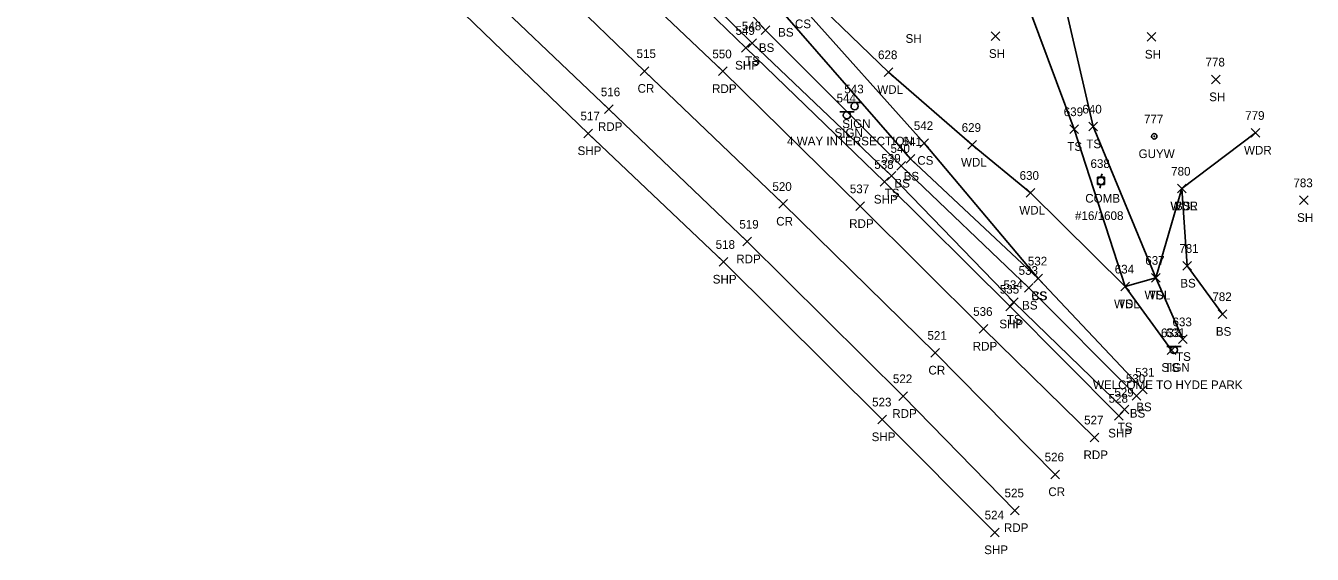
# Model space of a CAD drawing. Extents: x 1611034 to 1613847, y 761049 to 763902.
# Drawn here: x 1611761.1 to 1612057.6, y 762926.8 to 763048.6 of the extents above; entities that cross this region are included whole.
import ezdxf

# ---------------------------------------------------------------- set-up
doc = ezdxf.new("R2010")
doc.units = 0
for name, color, linetype in [('L_A', 7, 'Continuous'), ('L_I', 7, 'Continuous'), ('L_TIC', 7, 'Continuous'), ('LAWA', 7, 'Continuous'), ('LELB', 7, 'Continuous'), ('P_A', 7, 'Continuous'), ('P_I', 7, 'Continuous'), ('P_TIC', 7, 'Continuous'), ('PET', 7, 'Continuous'), ('PRC', 7, 'Continuous'), ('PSP', 7, 'Continuous'), ('S_A', 7, 'Continuous'), ('S_C', 7, 'Continuous'), ('S_I', 7, 'Continuous'), ('SSGN', 7, 'Continuous'), ('U_A', 7, 'Continuous'), ('U_C', 7, 'Continuous'), ('U_I', 7, 'Continuous'), ('UP', 7, 'Continuous'), ('UPGW', 7, 'Continuous')]:
    doc.layers.add(name, color=color, linetype=linetype)

msp = doc.modelspace()

# ---------------------------------------------------------------- linework, layer by layer
at = {"layer": 'L_TIC'}
for points in [[(1611930.63, 763046.56), (1611932.63, 763048.56)], [(1611932.63, 763046.56), (1611930.63, 763048.56)], [(1611927.51, 763043.56), (1611929.51, 763045.56)], [(1611929.51, 763043.56), (1611927.51, 763045.56)], [(1611983.61, 763045.19), (1611985.61, 763047.19)], [(1611985.61, 763045.19), (1611983.61, 763047.19)], [(1612019.56, 763045.03), (1612021.56, 763047.03)], [(1612021.56, 763045.03), (1612019.56, 763047.03)], [(1611958.95, 763036.9), (1611960.95, 763038.9)], [(1611960.95, 763036.9), (1611958.95, 763038.9)], [(1612034.39, 763035.21), (1612036.39, 763037.21)], [(1612036.39, 763035.21), (1612034.39, 763037.21)], [(1612001.76, 763023.77), (1612003.76, 763025.77)], [(1612003.76, 763023.77), (1612001.76, 763025.77)], [(1612006.15, 763024.37), (1612008.15, 763026.37)], [(1612008.15, 763024.37), (1612006.15, 763026.37)], [(1612043.55, 763022.91), (1612045.55, 763024.91)], [(1612045.55, 763022.91), (1612043.55, 763024.91)], [(1611967.15, 763020.56), (1611969.15, 763022.56)], [(1611969.15, 763020.56), (1611967.15, 763022.56)], [(1611978.24, 763020.14), (1611980.24, 763022.14)], [(1611980.24, 763020.14), (1611978.24, 763022.14)], [(1611964, 763016.91), (1611966, 763018.91)], [(1611966, 763016.91), (1611964, 763018.91)], [(1611959.67, 763013.03), (1611961.67, 763015.03)], [(1611961.67, 763013.03), (1611959.67, 763015.03)], [(1611961.87, 763015.31), (1611963.87, 763017.31)], [(1611963.87, 763015.31), (1611961.87, 763017.31)], [(1612026.56, 763010.05), (1612028.56, 763012.05)], [(1612028.56, 763010.05), (1612026.56, 763012.05)], [(1612026.56, 763010.05), (1612028.56, 763012.05)], [(1612028.56, 763010.05), (1612026.56, 763012.05)], [(1612026.56, 763010.05), (1612028.56, 763012.05)], [(1612028.56, 763010.05), (1612026.56, 763012.05)], [(1611991.68, 763009.08), (1611993.68, 763011.08)], [(1611993.68, 763009.08), (1611991.68, 763011.08)], [(1612054.66, 763007.38), (1612056.66, 763009.38)], [(1612056.66, 763007.38), (1612054.66, 763009.38)], [(1612027.77, 762992.25), (1612029.77, 762994.25)], [(1612029.77, 762992.25), (1612027.77, 762994.25)], [(1611993.45, 762989.34), (1611995.45, 762991.34)], [(1611995.45, 762989.34), (1611993.45, 762991.34)], [(1611993.45, 762989.34), (1611995.45, 762991.34)], [(1611995.45, 762989.34), (1611993.45, 762991.34)], [(1612020.56, 762989.5), (1612022.56, 762991.5)], [(1612022.56, 762989.5), (1612020.56, 762991.5)], [(1612020.56, 762989.5), (1612022.56, 762991.5)], [(1612022.56, 762989.5), (1612020.56, 762991.5)], [(1611991.31, 762987.18), (1611993.31, 762989.18)], [(1611993.31, 762987.18), (1611991.31, 762989.18)], [(1612013.52, 762987.49), (1612015.52, 762989.49)], [(1612015.52, 762987.49), (1612013.52, 762989.49)], [(1612013.52, 762987.49), (1612015.52, 762989.49)], [(1612015.52, 762987.49), (1612013.52, 762989.49)], [(1611987.81, 762983.91), (1611989.81, 762985.91)], [(1611989.81, 762983.91), (1611987.81, 762985.91)], [(1612035.97, 762981.13), (1612037.97, 762983.13)], [(1612037.97, 762981.13), (1612035.97, 762983.13)], [(1612026.83, 762975.33), (1612028.83, 762977.33)], [(1612028.83, 762975.33), (1612026.83, 762977.33)], [(1612024.16, 762972.81), (1612026.16, 762974.81)], [(1612026.16, 762972.81), (1612024.16, 762974.81)], [(1612017.61, 762963.73), (1612019.61, 762965.73)], [(1612019.61, 762963.73), (1612017.61, 762965.73)], [(1612016.14, 762962.27), (1612018.14, 762964.27)], [(1612018.14, 762962.27), (1612016.14, 762964.27)], [(1612013.39, 762959.1), (1612015.39, 762961.1)], [(1612015.39, 762959.1), (1612013.39, 762961.1)]]:
    msp.add_lwpolyline(points, dxfattribs=at)
at = {"layer": 'LAWA'}
for points in [[(1611776.19, 763209.71), (1611798.35, 763193.21), (1611821.91, 763171.59), (1611835.23, 763154.9), (1611840.73, 763150.36), (1611854.8, 763137.66), (1611869.74, 763122.61), (1611885.36, 763108.52), (1611898.9, 763094.55), (1611920.73, 763076.3), (1611936.34, 763060.75), (1611959.95, 763037.9), (1611979.24, 763021.14), (1611992.68, 763010.08), (1612014.52, 762988.49), (1612021.56, 762990.5), (1612027.56, 763011.05)], [(1612044.55, 763023.91), (1612027.56, 763011.05)]]:
    msp.add_lwpolyline(points, dxfattribs=at)
at = {"layer": 'LELB'}
for points in [[(1612017.14, 762963.27), (1611992.31, 762988.18), (1611962.87, 763016.31), (1611931.63, 763047.56), (1611908.18, 763073.24), (1611886.96, 763093.2), (1611860.29, 763119.05), (1611842.79, 763135.64), (1611817.54, 763159.12), (1611792.58, 763181.1), (1611769.85, 763202.31)], [(1612018.61, 762964.73), (1611994.45, 762990.34), (1611965, 763017.91), (1611936.07, 763051.1), (1611910.74, 763076.87), (1611888.16, 763094.11), (1611862.22, 763121.84), (1611845.65, 763138.15), (1611819.53, 763160.99), (1611794.46, 763183.41), (1611771.91, 763204.52)], [(1612014.39, 762960.1), (1611988.81, 762984.91), (1611960.67, 763014.03), (1611928.51, 763044.56), (1611903.94, 763068.78), (1611882.15, 763089), (1611856.04, 763113.65), (1611837.67, 763131.07), (1611812.66, 763153.54), (1611788.39, 763176.44), (1611765.16, 763197.77)], [(1612027.83, 762976.33), (1612021.56, 762990.5), (1612007.15, 763025.37), (1612000.41, 763054.68), (1611992.81, 763080.89), (1611980.83, 763110.42), (1611970.91, 763130.49), (1611962.53, 763149.06)], [(1612025.16, 762973.81), (1612014.52, 762988.49), (1612002.76, 763024.77), (1611990.56, 763057.6), (1611983.94, 763077.97), (1611968.18, 763110.4), (1611959.93, 763114.8), (1611955, 763122.87), (1611952.39, 763131.09), (1611945.26, 763129.19), (1611944.3, 763130.53), (1611943.6, 763140.75)], [(1611994.45, 762990.34), (1611968.15, 763021.56), (1611939.94, 763053.04), (1611912.82, 763078.99), (1611895.55, 763090.9), (1611891.53, 763096.94), (1611862.22, 763121.84)], [(1612027.56, 763011.05), (1612028.77, 762993.25), (1612036.97, 762982.13)]]:
    msp.add_lwpolyline(points, dxfattribs=at)
at = {"layer": 'P_TIC'}
for points in [[(1611926.06, 763042.5), (1611928.06, 763044.5)], [(1611928.06, 763042.5), (1611926.06, 763044.5)], [(1611902.68, 763037.16), (1611904.68, 763039.16)], [(1611904.68, 763037.16), (1611902.68, 763039.16)], [(1611920.8, 763037.1), (1611922.8, 763039.1)], [(1611922.8, 763037.1), (1611920.8, 763039.1)], [(1611894.49, 763028.35), (1611896.49, 763030.35)], [(1611896.49, 763028.35), (1611894.49, 763030.35)], [(1611889.74, 763022.79), (1611891.74, 763024.79)], [(1611891.74, 763022.79), (1611889.74, 763024.79)], [(1611958.05, 763011.61), (1611960.05, 763013.61)], [(1611960.05, 763011.61), (1611958.05, 763013.61)], [(1611934.64, 763006.53), (1611936.64, 763008.53)], [(1611936.64, 763006.53), (1611934.64, 763008.53)], [(1611952.4, 763006), (1611954.4, 763008)], [(1611954.4, 763006), (1611952.4, 763008)], [(1611926.37, 762997.83), (1611928.37, 762999.83)], [(1611928.37, 762997.83), (1611926.37, 762999.83)], [(1611920.91, 762993.17), (1611922.91, 762995.17)], [(1611922.91, 762993.17), (1611920.91, 762995.17)], [(1611986.98, 762982.85), (1611988.98, 762984.85)], [(1611988.98, 762982.85), (1611986.98, 762984.85)], [(1611980.88, 762977.72), (1611982.88, 762979.72)], [(1611982.88, 762977.72), (1611980.88, 762979.72)], [(1611969.73, 762972.2), (1611971.73, 762974.2)], [(1611971.73, 762972.2), (1611969.73, 762974.2)], [(1611962.34, 762962.21), (1611964.34, 762964.21)], [(1611964.34, 762962.21), (1611962.34, 762964.21)], [(1611957.53, 762956.84), (1611959.53, 762958.84)], [(1611959.53, 762956.84), (1611957.53, 762958.84)], [(1612012.06, 762957.69), (1612014.06, 762959.69)], [(1612014.06, 762957.69), (1612012.06, 762959.69)], [(1612006.41, 762952.69), (1612008.41, 762954.69)], [(1612008.41, 762952.69), (1612006.41, 762954.69)], [(1611997.37, 762944.17), (1611999.37, 762946.17)], [(1611999.37, 762944.17), (1611997.37, 762946.17)], [(1611988.07, 762935.88), (1611990.07, 762937.88)], [(1611990.07, 762935.88), (1611988.07, 762937.88)], [(1611983.49, 762930.79), (1611985.49, 762932.79)], [(1611985.49, 762930.79), (1611983.49, 762932.79)]]:
    msp.add_lwpolyline(points, dxfattribs=at)
at = {"layer": 'PET'}
for points in [[(1612007.41, 762953.69), (1611981.88, 762978.72), (1611953.4, 763007), (1611921.8, 763038.1), (1611897.05, 763061.61), (1611875.73, 763082.09), (1611849.32, 763106.5), (1611830.38, 763124.18), (1611806.13, 763146.18), (1611781.49, 763169.41), (1611758.07, 763190.79)], [(1611742.95, 763171.95), (1611773.98, 763143.16), (1611800.57, 763118.45), (1611832.55, 763088.78), (1611862.37, 763060.94), (1611895.49, 763029.35), (1611927.37, 762998.83), (1611963.34, 762963.21), (1611989.07, 762936.88)]]:
    msp.add_lwpolyline(points, dxfattribs=at)
at = {"layer": 'PRC'}
msp.add_lwpolyline([(1611750.53, 763181.03), (1611781.55, 763152.75), (1611808.47, 763127.7), (1611840.68, 763098.05), (1611871.03, 763069.71), (1611903.68, 763038.16), (1611935.64, 763007.53), (1611970.73, 762973.2), (1611998.37, 762945.17)], dxfattribs=at)
at = {"layer": 'PSP'}
for points in [[(1612013.06, 762958.69), (1611987.98, 762983.85), (1611959.05, 763012.61), (1611927.06, 763043.5), (1611902.53, 763067.25), (1611880.81, 763087.35), (1611854.34, 763111.86), (1611835.7, 763129.09), (1611811.01, 763152.07), (1611786.17, 763174.66), (1611763.42, 763195.74)], [(1611737.63, 763166.68), (1611769.14, 763137.5), (1611795.96, 763113), (1611827.31, 763083.61), (1611857.87, 763055.56), (1611890.74, 763023.79), (1611921.91, 762994.17), (1611958.53, 762957.84), (1611984.49, 762931.79)]]:
    msp.add_lwpolyline(points, dxfattribs=at)
at = {"layer": 'SSGN'}
for p, q in [((1611950.51, 763030.88), (1611953.84, 763030.88)), ((1611952.15, 763030.04), (1611952.15, 763030.04)), ((1611948.72, 763028.79), (1611952.06, 763028.79)), ((1611950.37, 763027.96), (1611950.37, 763027.96)), ((1612024.08, 762974.68), (1612027.41, 762974.68)), ((1612025.72, 762973.85), (1612025.72, 762973.85))]:
    msp.add_line(p, q, dxfattribs=at)
for centre in [(1611952.15, 763030.04), (1611950.37, 763027.96), (1612025.72, 762973.85)]:
    msp.add_circle(centre, 0.833, dxfattribs=at)
at = {"layer": 'UP'}
for p, q in [((1612008.1, 763011.99), (1612008.1, 763013.66)), ((1612008.1, 763013.66), (1612009.76, 763013.66)), ((1612009.76, 763011.99), (1612008.1, 763011.99)), ((1612008.68, 763011.16), (1612008.93, 763011.99)), ((1612009.18, 763014.49), (1612008.93, 763013.66)), ((1612008.93, 763012.82), (1612008.93, 763012.82)), ((1612009.76, 763013.66), (1612009.76, 763011.99))]:
    msp.add_line(p, q, dxfattribs=at)
msp.add_circle((1612008.93, 763012.82), 0.833, dxfattribs=at)
at = {"layer": 'UPGW'}
for radius in [0.625, 0.0833]:
    msp.add_circle((1612021.22, 763023.1), radius, dxfattribs=at)

# ---------------------------------------------------------------- texts
at = {"layer": 'L_A'}
for s, p in [('BS', (1611934.51, 763046.1)), ('CS', (1611938.39, 763048.04)), ('BS', (1611930.07, 763042.56)), ('SH', (1611963.88, 763044.66)), ('TS', (1611926.92, 763039.56)), ('SH', (1611983.1, 763041.19)), ('SH', (1612019.05, 763041.03)), ('WDL', (1611957.37, 763032.9)), ('SH', (1612033.88, 763031.21)), ('TS', (1612001.17, 763019.77)), ('TS', (1612005.56, 763020.37)), ('WDR', (1612041.91, 763018.91)), ('CS', (1611966.59, 763016.56)), ('WDL', (1611976.66, 763016.14)), ('BS', (1611963.44, 763012.91)), ('BS', (1611961.32, 763011.31)), ('TS', (1611959.08, 763009.03)), ('WDL', (1611990.1, 763005.08)), ('WDR', (1612024.92, 763006.05)), ('WDL', (1612024.97, 763006.05)), ('BS', (1612026, 763006.05)), ('SH', (1612054.14, 763003.38)), ('BS', (1612027.22, 762988.25)), ('BS', (1611990.75, 762983.18)), ('CS', (1611992.89, 762985.34)), ('BS', (1611992.89, 762985.34)), ('WDL', (1612011.94, 762983.49)), ('TS', (1612012.93, 762983.49)), ('WDL', (1612018.98, 762985.5)), ('TS', (1612019.97, 762985.5)), ('TS', (1611987.22, 762979.91)), ('BS', (1612035.41, 762977.13)), ('TS', (1612026.24, 762971.33)), ('TS', (1612023.57, 762968.81)), ('BS', (1612017.06, 762959.73)), ('BS', (1612015.58, 762958.27)), ('TS', (1612012.79, 762955.1))]:
    msp.add_text(s, height=2, dxfattribs=at).set_placement(p)
at = {"layer": 'L_I'}
for s, p in [('548', (1611926.15, 763047.56)), ('628', (1611957.54, 763040.9)), ('778', (1612033.03, 763039.21)), ('639', (1612000.35, 763027.77)), ('640', (1612004.65, 763028.37)), ('542', (1611965.79, 763024.56)), ('779', (1612042.18, 763026.91)), ('629', (1611976.82, 763024.14)), ('540', (1611960.43, 763019.31)), ('541', (1611963.21, 763020.91)), ('539', (1611958.3, 763017.03)), ('630', (1611990.18, 763013.08)), ('780', (1612025.11, 763014.05)), ('780', (1612025.11, 763014.05)), ('780', (1612025.11, 763014.05)), ('783', (1612053.29, 763011.38)), ('781', (1612026.98, 762996.25)), ('532', (1611992.08, 762993.34)), ('532', (1611992.08, 762993.34)), ('637', (1612019.15, 762993.5)), ('637', (1612019.15, 762993.5)), ('533', (1611989.95, 762991.18)), ('634', (1612012.11, 762991.49)), ('634', (1612012.11, 762991.49)), ('534', (1611986.45, 762987.91)), ('782', (1612034.61, 762985.13)), ('633', (1612025.42, 762979.33)), ('632', (1612022.75, 762976.81)), ('530', (1612014.69, 762966.27)), ('531', (1612016.82, 762967.73)), ('529', (1612012.02, 762963.1))]:
    msp.add_text(s, height=2, dxfattribs=at).set_placement(p)
at = {"layer": 'P_A'}
for s, p in [('SHP', (1611924.6, 763038.5)), ('CR', (1611902.11, 763033.16)), ('RDP', (1611919.29, 763033.1)), ('RDP', (1611892.97, 763024.35)), ('SHP', (1611888.28, 763018.79)), ('SHP', (1611956.58, 763007.61)), ('CR', (1611934.07, 763002.53)), ('RDP', (1611950.89, 763002)), ('RDP', (1611924.86, 762993.83)), ('SHP', (1611919.44, 762989.17)), ('SHP', (1611985.51, 762978.85)), ('RDP', (1611979.37, 762973.72)), ('CR', (1611969.16, 762968.2)), ('RDP', (1611960.83, 762958.21)), ('SHP', (1612010.6, 762953.69)), ('SHP', (1611956.07, 762952.84)), ('RDP', (1612004.9, 762948.69)), ('CR', (1611996.8, 762940.17)), ('RDP', (1611986.56, 762931.88)), ('SHP', (1611982.02, 762926.79))]:
    msp.add_text(s, height=2, dxfattribs=at).set_placement(p)
at = {"layer": 'P_I'}
for s, p in [('549', (1611924.69, 763046.5)), ('515', (1611901.88, 763041.16)), ('550', (1611919.35, 763041.1)), ('516', (1611893.64, 763032.35)), ('517', (1611888.95, 763026.79)), ('538', (1611956.68, 763015.61)), ('520', (1611933.19, 763010.53)), ('537', (1611951.04, 763010)), ('519', (1611925.57, 763001.83)), ('518', (1611920.11, 762997.17)), ('535', (1611985.61, 762986.85)), ('536', (1611979.47, 762981.72)), ('521', (1611968.93, 762976.2)), ('522', (1611960.97, 762966.21)), ('523', (1611956.17, 762960.84)), ('528', (1612010.7, 762961.69)), ('527', (1612005.04, 762956.69)), ('526', (1611995.95, 762948.17)), ('525', (1611986.71, 762939.88)), ('524', (1611982.12, 762934.79))]:
    msp.add_text(s, height=2, dxfattribs=at).set_placement(p)
at = {"layer": 'S_A'}
for p in [(1611949.29, 763025.02), (1611947.51, 763022.94), (1612022.86, 762968.83)]:
    msp.add_text('SIGN', height=2, dxfattribs=at).set_placement(p)
at = {"layer": 'S_C'}
for s, p in [('4 WAY INTERSECTION', (1611936.58, 763021.02)), ('WELCOME TO HYDE PARK', (1612007.09, 762964.83))]:
    msp.add_text(s, height=2, dxfattribs=at).set_placement(p)
at = {"layer": 'S_I'}
for s, p in [('544', (1611947.99, 763030.94)), ('543', (1611949.77, 763033.02)), ('631', (1612023.86, 762976.83))]:
    msp.add_text(s, height=2, dxfattribs=at).set_placement(p)
at = {"layer": 'U_A'}
for s, p in [('GUYW', (1612017.61, 763018.1)), ('COMB', (1612005.31, 763007.82))]:
    msp.add_text(s, height=2, dxfattribs=at).set_placement(p)
at = {"layer": 'U_C'}
msp.add_text('#16/1608', height=2, dxfattribs=at).set_placement((1612002.96, 763003.82))
at = {"layer": 'U_I'}
for s, p in [('777', (1612018.85, 763026.1)), ('638', (1612006.52, 763015.82))]:
    msp.add_text(s, height=2, dxfattribs=at).set_placement(p)

doc.saveas('drawing.dxf')
